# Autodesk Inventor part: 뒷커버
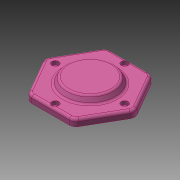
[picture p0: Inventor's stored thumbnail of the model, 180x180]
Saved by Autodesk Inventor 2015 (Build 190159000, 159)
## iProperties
Created: 2013-02
Part Number: 뒷커버
Document SubType Name: Modeling
Density: 1 g/cm^3
Material: 일반
Appearance: 분홍색
Author: 한국산업디자인학원[gmhk.co.kr]
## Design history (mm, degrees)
sketch "스케치1" dims "d37" = 105
  geometry: L1 (50.191, -4)-(28.559, -41.466); L2 (21.631, -45.466)-(-21.631, -45.466); L3 (-28.559, -41.466)-(-50.191, -4); L4 (-50.191, 4)-(-28.559, 41.466); L5 (-21.631, 45.466)-(21.631, 45.466); L6 (28.559, 41.466)-(50.191, 4); C1 r 30 at (0, 0); A1 r 8 centre (-21.631, 37.466) between (-21.631, 45.466) and (-28.559, 41.466); A2 r 8 centre (21.631, 37.466) between (28.559, 41.466) and (21.631, 45.466); A3 r 8 centre (43.262, 0) between (50.191, -4) and (50.191, 4); A4 r 8 centre (21.631, -37.466) between (21.631, -45.466) and (28.559, -41.466); A5 r 8 centre (-21.631, -37.466) between (-28.559, -41.466) and (-21.631, -45.466); A6 r 8 centre (-43.262, 0) between (-50.191, 4) and (-50.191, -4); 9 further points
  constraints: 12 end point, 12 point on circle, 12 point on line, 12 tangent, 7 centre point, 5 equal radius, 3 coincident, 1 horizontal, 1 horizontal alignment, 15 other
  dimensions: "d39" = 60 diameter of C1; "d40" = 8 radius of A1
extrude "돌출1" new body sketch "스케치1" distance "d0" = 8; taper "d1" = 0 deg
sketch "스케치2"
  geometry: C1 r 30 at (0, 0); 1 further point
  constraints: 1 centre point, 1 coincident
  dimensions: "d2" = 60 diameter of C1
extrude "돌출2" join sketch "스케치2" distance "d3" = 7; taper "d4" = -30 deg
sketch "스케치3"
  geometry: C1 r 30 at (0, 0) reference; A1 r 40 centre (0, 0) between (0, 40) and (-40, 0); 2 further points
  constraints: 4 point on circle, 2 horizontal alignment, 2 vertical alignment, 1 centre point, 1 coincident
  dimensions: "d47" = 80 diameter of A1
hole "구멍2" sketch "스케치3" at (0, 40), (-40, 0), (0, -40), (40, 0) diameter "d14" = 4.5; stored, may be unused: countersink angle "d18" = 90 deg, drill point angle "d20" = 118 deg; dims "d15" = 6, "d16" = 8, "d17" = 4.4, "d19" = 20
extrude "돌출3" join sketch "스케치1" distance "d21" = 12; taper "d22" = 0 deg
hole "구멍3" diameter "d25" = 30; stored, may be unused: countersink angle "d29" = 90 deg, drill point angle "d31" = 0 deg; dims "d26" = 6, "d27" = 42, "d28" = 13, "d30" = 16, "d50" = 10, "d51" = 10
fillet "모깎기1" dims "d32" = 3, "d33" = 1
chamfer "모따기1" distance "d34" = 1; stored, may be unused: second distance "d35" = 2, angle "d36" = 45 deg
chamfer "모따기2" distance "d43" = 1; stored, may be unused: second distance "d44" = 2, angle "d45" = 45 deg
fillet "모깎기2" dims "d46" = 3
node "솔리드1"
